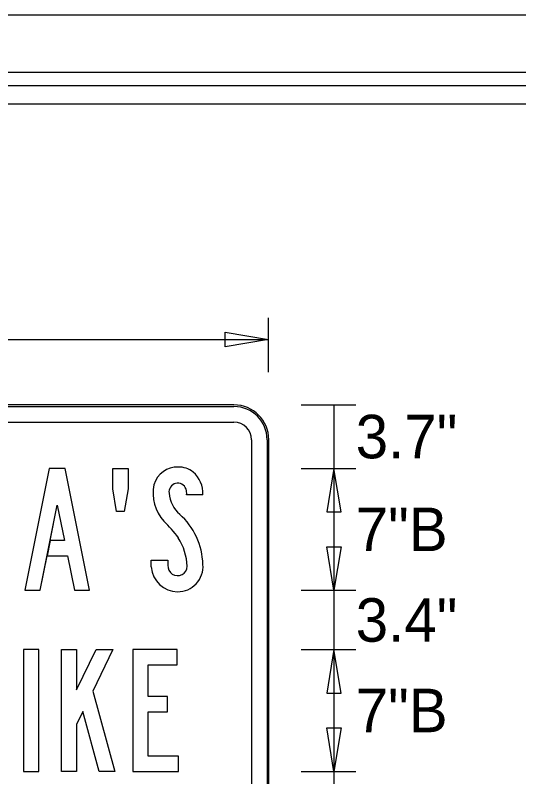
# Model space of a CAD drawing. Extents: x 17890628 to 17890844, y 17897693 to 17898031.
# Drawn here: x 17890818.49 to 17890826.19, y 17897988.15 to 17897999.81 of the extents above; entities that cross this region are included whole.
import ezdxf

# ---------------------------------------------------------------- set-up
doc = ezdxf.new("R2010")
doc.units = 0
for name, color, linetype in [('GSColorFill', 7, 'Continuous'), ('GSDims', 7, 'Continuous'), ('PlotBorder_dp', 7, 'Continuous'), ('SheetBorder_dp', 7, 'Continuous'), ('SheetLinesMisc2_dp', 7, 'Continuous')]:
    doc.layers.add(name, color=color, linetype=linetype)

msp = doc.modelspace()

# ---------------------------------------------------------------- linework, layer by layer
at = {"layer": 'GSColorFill'}
for p, q in [((17890821.835, 17897993.845), (17890812.234, 17897993.845)), ((17890821.835, 17897993.845), (17890812.234, 17897993.845)), ((17890821.835, 17897993.845), (17890812.234, 17897993.845)), ((17890812.234, 17897993.819), (17890821.835, 17897993.819)), ((17890812.234, 17897993.579), (17890821.835, 17897993.579)), ((17890822.101, 17897993.312), (17890822.101, 17897981.578)), ((17890822.341, 17897993.312), (17890822.341, 17897981.578)), ((17890822.368, 17897981.578), (17890822.368, 17897993.312)), ((17890822.368, 17897981.578), (17890822.368, 17897993.312)), ((17890822.368, 17897981.578), (17890822.368, 17897993.312)), ((17890821.358, 17897992.469), (17890821.11, 17897992.469)), ((17890821.358, 17897992.469), (17890821.11, 17897992.469)), ((17890821.358, 17897992.469), (17890821.11, 17897992.469)), ((17890820.568, 17897991.468), (17890820.821, 17897991.468)), ((17890820.568, 17897991.468), (17890820.821, 17897991.468)), ((17890820.568, 17897991.468), (17890820.821, 17897991.468))]:
    msp.add_line(p, q, dxfattribs=at)
for points in [[(17890819.286, 17897991.534), (17890819.392, 17897991.006), (17890819.626, 17897991.006), (17890819.252, 17897992.871), (17890819.008, 17897992.871), (17890818.634, 17897991.006), (17890818.868, 17897991.006), (17890818.974, 17897991.534)], [(17890819.021, 17897991.767), (17890818.974, 17897991.534), (17890819.286, 17897991.534), (17890819.392, 17897991.006), (17890819.626, 17897991.006), (17890819.252, 17897992.871), (17890819.008, 17897992.871), (17890818.634, 17897991.006), (17890818.868, 17897991.006), (17890819.13, 17897992.31), (17890819.239, 17897991.767)], [(17890819.021, 17897991.767), (17890818.974, 17897991.534), (17890819.286, 17897991.534), (17890819.392, 17897991.006), (17890819.626, 17897991.006), (17890819.252, 17897992.871), (17890819.008, 17897992.871), (17890818.634, 17897991.006), (17890818.868, 17897991.006), (17890819.13, 17897992.31), (17890819.239, 17897991.767)], [(17890819.98, 17897992.557), (17890819.98, 17897992.871), (17890820.214, 17897992.871), (17890820.214, 17897992.557), (17890820.155, 17897992.21), (17890820.038, 17897992.21)], [(17890819.98, 17897992.557), (17890819.98, 17897992.871), (17890820.214, 17897992.871), (17890820.214, 17897992.557), (17890820.155, 17897992.21), (17890820.038, 17897992.21)], [(17890819.98, 17897992.557), (17890819.98, 17897992.871), (17890820.214, 17897992.871), (17890820.214, 17897992.557), (17890820.155, 17897992.21), (17890820.038, 17897992.21)], [(17890819.13, 17897992.31), (17890819.239, 17897991.767), (17890819.021, 17897991.767)], [(17890818.846, 17897990.099), (17890818.616, 17897990.099), (17890818.616, 17897988.233), (17890818.846, 17897988.233)], [(17890818.846, 17897990.099), (17890818.616, 17897990.099), (17890818.616, 17897988.233), (17890818.846, 17897988.233)], [(17890818.846, 17897990.099), (17890818.616, 17897990.099), (17890818.616, 17897988.233), (17890818.846, 17897988.233)], [(17890819.195, 17897988.233), (17890819.195, 17897990.099), (17890819.425, 17897990.099), (17890819.425, 17897989.482), (17890819.724, 17897990.099), (17890819.98, 17897990.099), (17890819.672, 17897989.463), (17890820.013, 17897988.233), (17890819.774, 17897988.233), (17890819.52, 17897989.15), (17890819.425, 17897988.953), (17890819.425, 17897988.233)], [(17890819.195, 17897988.233), (17890819.195, 17897990.099), (17890819.425, 17897990.099), (17890819.425, 17897989.482), (17890819.724, 17897990.099), (17890819.98, 17897990.099), (17890819.672, 17897989.463), (17890820.013, 17897988.233), (17890819.774, 17897988.233), (17890819.52, 17897989.15), (17890819.425, 17897988.953), (17890819.425, 17897988.233)], [(17890819.195, 17897988.233), (17890819.195, 17897990.099), (17890819.425, 17897990.099), (17890819.425, 17897989.482), (17890819.724, 17897990.099), (17890819.98, 17897990.099), (17890819.672, 17897989.463), (17890820.013, 17897988.233), (17890819.774, 17897988.233), (17890819.52, 17897989.15), (17890819.425, 17897988.953), (17890819.425, 17897988.233)], [(17890820.519, 17897988.466), (17890820.519, 17897989.146), (17890820.819, 17897989.146), (17890820.819, 17897989.38), (17890820.519, 17897989.38), (17890820.519, 17897989.866), (17890820.967, 17897989.866), (17890820.967, 17897990.099), (17890820.289, 17897990.099), (17890820.289, 17897988.233), (17890820.988, 17897988.233), (17890820.988, 17897988.466)], [(17890820.519, 17897988.466), (17890820.519, 17897989.146), (17890820.819, 17897989.146), (17890820.819, 17897989.38), (17890820.519, 17897989.38), (17890820.519, 17897989.866), (17890820.967, 17897989.866), (17890820.967, 17897990.099), (17890820.289, 17897990.099), (17890820.289, 17897988.233), (17890820.988, 17897988.233), (17890820.988, 17897988.466)], [(17890820.519, 17897988.466), (17890820.519, 17897989.146), (17890820.819, 17897989.146), (17890820.819, 17897989.38), (17890820.519, 17897989.38), (17890820.519, 17897989.866), (17890820.967, 17897989.866), (17890820.967, 17897990.099), (17890820.289, 17897990.099), (17890820.289, 17897988.233), (17890820.988, 17897988.233), (17890820.988, 17897988.466)]]:
    msp.add_lwpolyline(points, close=True, dxfattribs=at)
for radius, start in [(0.533, 360), (0.533, 360), (0.533, 0), (0.507, 0), (0.267, 360)]:
    msp.add_arc((17890821.835, 17897993.312), radius, start, 90, dxfattribs=at)
for centre, major_axis, start_param, end_param in [((17890820.966, 17897992.514), (0, 0.378), 6.238773, 7.56343), ((17890820.966, 17897992.514), (0, 0.378), 6.238773, 7.56343), ((17890820.966, 17897992.514), (0, 0.378), 6.238773, 7.56343), ((17890820.991, 17897992.539), (0, 0.354), 5.608184, 6.306169), ((17890820.991, 17897992.539), (0, 0.354), 5.608184, 6.306169), ((17890820.991, 17897992.539), (0, 0.354), 5.608184, 6.306169), ((17890820.946, 17897992.492), (0, 0.419), 4.658508, 5.592972), ((17890820.946, 17897992.492), (0, 0.419), 4.658508, 5.592972), ((17890820.946, 17897992.492), (0, 0.419), 4.658508, 5.592972), ((17890821.234, 17897992.496), (0, 0.647), 1.37325, 2.303641), ((17890821.234, 17897992.496), (0, 0.647), 1.37325, 2.303641), ((17890821.234, 17897992.496), (0, 0.647), 1.37325, 2.303641), ((17890820.974, 17897992.511), (0, 0.136), 5.044718, 8.004311), ((17890820.974, 17897992.511), (0, 0.136), 5.044718, 8.004311), ((17890820.974, 17897992.511), (0, 0.136), 5.044718, 8.004311), ((17890820.895, 17897992.488), (0, 0.219), 4.624973, 5.022668), ((17890820.895, 17897992.488), (0, 0.219), 4.624973, 5.022668), ((17890820.895, 17897992.488), (0, 0.219), 4.624973, 5.022668), ((17890821.323, 17897992.539), (0, 0.491), 1.669462, 2.420236), ((17890821.323, 17897992.539), (0, 0.491), 1.669462, 2.420236), ((17890821.323, 17897992.539), (0, 0.491), 1.669462, 2.420236), ((17890820.301, 17897991.366), (0, 1.075), 4.746366, 5.558127), ((17890820.301, 17897991.366), (0, 1.075), 4.746366, 5.558127), ((17890820.301, 17897991.366), (0, 1.075), 4.746366, 5.558127), ((17890819.715, 17897990.893), (0, 1.58), 5.330576, 5.546891), ((17890819.715, 17897990.893), (0, 1.58), 5.330576, 5.546891), ((17890819.715, 17897990.893), (0, 1.58), 5.330576, 5.546891), ((17890820.248, 17897991.332), (0, 0.885), 4.761194, 5.279997), ((17890820.248, 17897991.332), (0, 0.885), 4.761194, 5.279997), ((17890820.248, 17897991.332), (0, 0.885), 4.761194, 5.279997), ((17890803.074, 17897991.088), (0, 17.764), 4.727928, 4.733783), ((17890803.074, 17897991.088), (0, 17.764), 4.727928, 4.733783), ((17890803.074, 17897991.088), (0, 17.764), 4.727928, 4.733783), ((17890820.971, 17897991.381), (0, 0.151), 1.518722, 4.675676), ((17890820.971, 17897991.381), (0, 0.151), 1.518722, 4.675676), ((17890820.971, 17897991.381), (0, 0.151), 1.518722, 4.675676), ((17890821.88, 17897991.441), (0, 1.075), 1.545917, 1.619781), ((17890821.88, 17897991.441), (0, 1.075), 1.545917, 1.619781), ((17890821.88, 17897991.441), (0, 1.075), 1.545917, 1.619781), ((17890820.978, 17897991.373), (0, 0.389), 3.127116, 4.786666), ((17890820.978, 17897991.373), (0, 0.389), 3.127116, 4.786666), ((17890820.978, 17897991.373), (0, 0.389), 3.127116, 4.786666), ((17890820.971, 17897991.393), (0, 0.409), 1.642579, 3.144332), ((17890820.971, 17897991.393), (0, 0.409), 1.642579, 3.144332), ((17890820.971, 17897991.393), (0, 0.409), 1.642579, 3.144332)]:
    msp.add_ellipse(centre, major_axis=major_axis, ratio=0.985, start_param=start_param, end_param=end_param, dxfattribs=at)
at = {"layer": 'GSDims'}
for p, q in [((17890822.365, 17897994.346), (17890822.365, 17897995.179)), ((17890811.698, 17897994.846), (17890822.365, 17897994.846)), ((17890822.865, 17897993.846), (17890823.698, 17897993.846)), ((17890823.365, 17897993.846), (17890823.365, 17897992.873)), ((17890822.865, 17897992.873), (17890823.698, 17897992.873)), ((17890822.865, 17897992.873), (17890823.698, 17897992.873)), ((17890823.365, 17897992.873), (17890823.365, 17897991.006)), ((17890822.865, 17897991.006), (17890823.698, 17897991.006)), ((17890822.865, 17897991.006), (17890823.698, 17897991.006)), ((17890823.365, 17897991.006), (17890823.365, 17897990.099)), ((17890822.865, 17897990.099), (17890823.698, 17897990.099)), ((17890822.865, 17897990.099), (17890823.698, 17897990.099)), ((17890823.365, 17897990.099), (17890823.365, 17897988.233)), ((17890822.865, 17897988.233), (17890823.698, 17897988.233)), ((17890822.865, 17897988.233), (17890823.698, 17897988.233)), ((17890823.365, 17897988.233), (17890823.365, 17897987.316))]:
    msp.add_line(p, q, dxfattribs=at)
for points in [[(17890822.365, 17897994.846), (17890821.698, 17897994.735), (17890821.698, 17897994.957)], [(17890823.365, 17897992.873), (17890823.254, 17897992.206), (17890823.476, 17897992.206)], [(17890823.365, 17897991.006), (17890823.254, 17897991.673), (17890823.476, 17897991.673)], [(17890823.365, 17897990.099), (17890823.254, 17897989.433), (17890823.476, 17897989.433)], [(17890823.365, 17897988.233), (17890823.254, 17897988.899), (17890823.476, 17897988.899)]]:
    msp.add_lwpolyline(points, close=True, dxfattribs=at)
at = {"layer": 'PlotBorder_dp'}
msp.add_lwpolyline([(17890700.471, 17897907.61), (17890843.989, 17897907.61), (17890843.989, 17897999.809), (17890700.471, 17897999.809)], close=True, dxfattribs=at)
at = {"layer": 'SheetBorder_dp'}
msp.add_line((17890705.254, 17897998.94), (17890839.205, 17897998.94), dxfattribs=at)
at = {"layer": 'SheetLinesMisc2_dp'}
for p, q in [((17890705.5, 17897998.732), (17890839.233, 17897998.732)), ((17890793.11, 17897998.455), (17890838.594, 17897998.455))]:
    msp.add_line(p, q, dxfattribs=at)

# ---------------------------------------------------------------- texts
at = {"layer": 'GSDims'}
for s, p in [('3.7"', (17890823.698, 17897993.026)), ('7"B', (17890823.698, 17897991.606)), ('3.4"', (17890823.698, 17897990.219)), ('7"B', (17890823.698, 17897988.833))]:
    msp.add_text(s, height=0.6667, dxfattribs=at).set_placement(p)

doc.saveas('drawing.dxf')
